Omron CX-Programmer project NuevoProyecto (CX-Programmer 9.50)

# PLC NewPLC1: CQM1 CPU21

## Program P7_4 (no task)
Local symbols
Ab 100.01 BOOL
As 100.00 BOOL
B 100.02 BOOL
C 100.03 BOOL
Etapa_0 10.00 BOOL
Etapa_1 10.01 BOOL
Etapa_10 10.07 BOOL
Etapa_11 10.08 BOOL
Etapa_12 10.09 BOOL
Etapa_13 10.10 BOOL
Etapa_2 10.02 BOOL
Etapa_3 10.03 BOOL
Etapa_4 10.04 BOOL
Etapa_5 10.05 BOOL
Etapa_E1 10.06 BOOL
Etapa_S1 10.11 BOOL
FS_Etapa_2 15.00 BOOL
FS_Etapa_4 15.01 BOOL
a_0 0.01 BOOL
a_1 0.02 BOOL
a_2 0.03 BOOL
b_0 0.04 BOOL
b_1 0.05 BOOL
c_0 0.06 BOOL
c_1 0.07 BOOL
m 0.00 BOOL

### Section Secci๓n1_Ecuaciones_Prog_principal
; Programa principal (Etapas 0 ... 5)

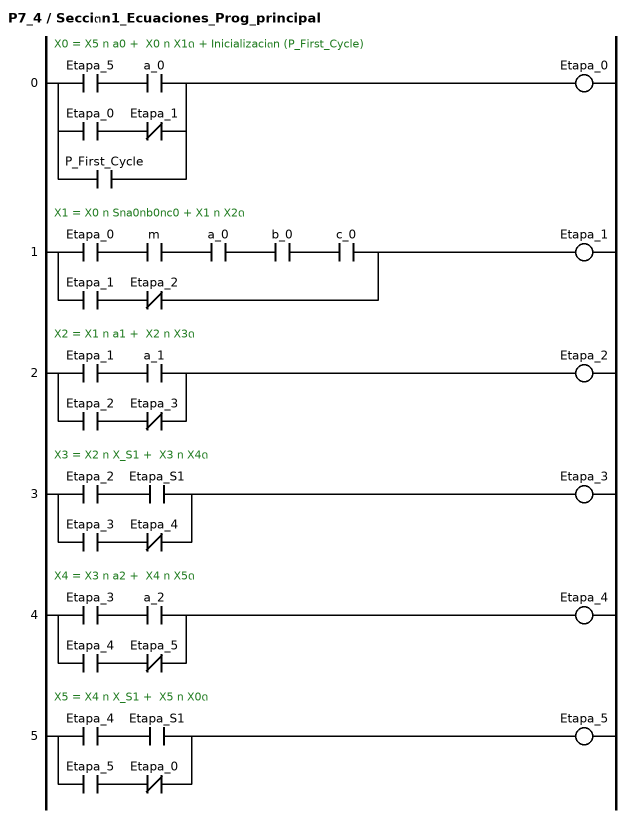
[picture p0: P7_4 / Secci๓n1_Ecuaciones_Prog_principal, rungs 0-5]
; rung 0: X0 = X5 ท a0 +  X0 ท X1ด + Inicializaci๓n (P_First_Cycle)
LD Etapa_5
AND a_0
LD Etapa_0
ANDNOT Etapa_1
ORLD
OR P_First_Cycle
OUT Etapa_0
; rung 1: X1 = X0 ท Sทa0ทb0ทc0 + X1 ท X2ด
LD Etapa_0
AND m
AND a_0
AND b_0
AND c_0
LD Etapa_1
ANDNOT Etapa_2
ORLD
OUT Etapa_1
; rung 2: X2 = X1 ท a1 +  X2 ท X3ด
LD Etapa_1
AND a_1
LD Etapa_2
ANDNOT Etapa_3
ORLD
OUT Etapa_2
; rung 3: X3 = X2 ท X_S1 +  X3 ท X4ด
LD Etapa_2
AND Etapa_S1
LD Etapa_3
ANDNOT Etapa_4
ORLD
OUT Etapa_3
; rung 4: X4 = X3 ท a2 +  X4 ท X5ด
LD Etapa_3
AND a_2
LD Etapa_4
ANDNOT Etapa_5
ORLD
OUT Etapa_4
; rung 5: X5 = X4 ท X_S1 +  X5 ท X0ด
LD Etapa_4
AND Etapa_S1
LD Etapa_5
ANDNOT Etapa_0
ORLD
OUT Etapa_5

### Section Secci๓n2_Ecuaciones_Macroetapa

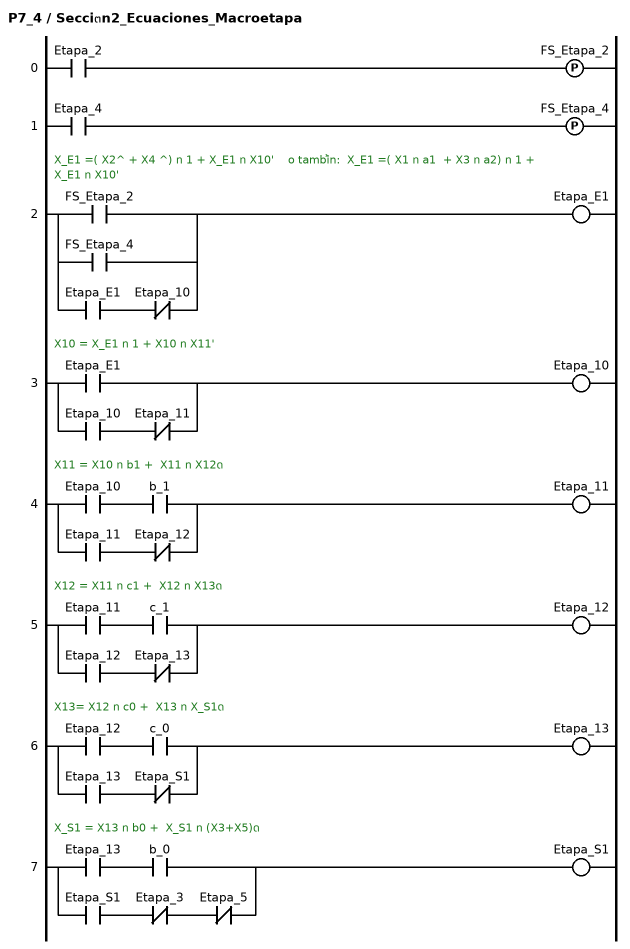
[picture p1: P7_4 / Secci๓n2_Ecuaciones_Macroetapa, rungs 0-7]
; rung 0
LD Etapa_2
DIFU(13) FS_Etapa_2
; rung 1
LD Etapa_4
DIFU(13) FS_Etapa_4
; rung 2: X_E1 =( X2^ + X4 ^) ท 1 + X_E1 ท X10'    o tambi้n:  X_E1 =( X1 ท a1  + X3 ท a2) ท 1 + X_E1 ท X10'
LD FS_Etapa_2
OR FS_Etapa_4
LD Etapa_E1
ANDNOT Etapa_10
ORLD
OUT Etapa_E1
; rung 3: X10 = X_E1 ท 1 + X10 ท X11'
LD Etapa_E1
LD Etapa_10
ANDNOT Etapa_11
ORLD
OUT Etapa_10
; rung 4: X11 = X10 ท b1 +  X11 ท X12ด
LD Etapa_10
AND b_1
LD Etapa_11
ANDNOT Etapa_12
ORLD
OUT Etapa_11
; rung 5: X12 = X11 ท c1 +  X12 ท X13ด
LD Etapa_11
AND c_1
LD Etapa_12
ANDNOT Etapa_13
ORLD
OUT Etapa_12
; rung 6: X13= X12 ท c0 +  X13 ท X_S1ด
LD Etapa_12
AND c_0
LD Etapa_13
ANDNOT Etapa_S1
ORLD
OUT Etapa_13
; rung 7: X_S1 = X13 ท b0 +  X_S1 ท (X3+X5)ด
LD Etapa_13
AND b_0
LD Etapa_S1
ANDNOT Etapa_3
ANDNOT Etapa_5
ORLD
OUT Etapa_S1

### Section Secci๓n3_Salidas

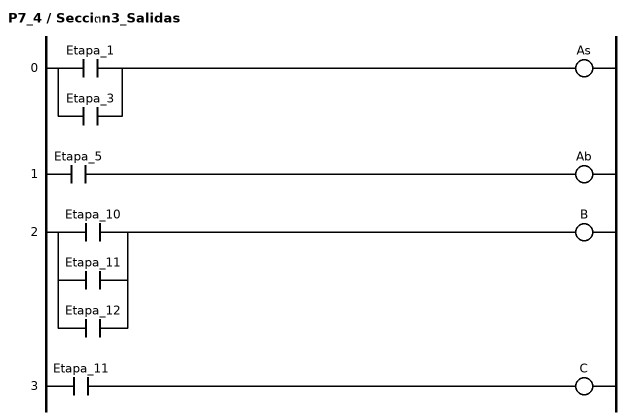
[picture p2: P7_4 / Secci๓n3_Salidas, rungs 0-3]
; rung 0
LD Etapa_1
OR Etapa_3
OUT As
; rung 1
LD Etapa_5
OUT Ab
; rung 2
LD Etapa_10
OR Etapa_11
OR Etapa_12
OUT B
; rung 3
LD Etapa_11
OUT C

### Section Secci๓n4_END
; rung 0: Fin de programa
END(01)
